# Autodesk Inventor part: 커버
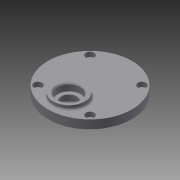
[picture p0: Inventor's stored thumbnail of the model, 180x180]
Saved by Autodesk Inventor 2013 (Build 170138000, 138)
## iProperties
Created: 2015-07
Part Number: 커버
Material: 일반
Document SubType Name: Modeling
Designer: user
Density: 1 g/cm^3
Author: user
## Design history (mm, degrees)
sketch "스케치1"
  geometry: C1 r 40 at (0, 0); 1 further point
  constraints: 1 centre point, 1 coincident
  dimensions: "d0" = 80 diameter of C1
extrude "돌출1" new body sketch "스케치1" distance "d1" = 9; taper "d2" = 0 deg
sketch "스케치2"
  geometry: L1 (0, 0)-(0, 11); L2 (0, 0)-(0, -20); C1 r 40 at (0, 0) reference; C2 r 14 at (0, -20); C3 r 14 at (0, 11)
  constraints: 4 end point, 2 centre point, 2 coincident, 1 collinear, 1 vertical
  dimensions: "d3" = 11 distance of L1.start L1.end; "d4" = 20 distance of L1.start L2.end; "d6" = 28 diameter of C2; "d7" = 28 diameter of C3
extrude "돌출2" join sketch "스케치2" distance "d8" = 3; taper "d9" = 0 deg
sketch "스케치3"
  geometry: C1 r 14 at (0, 0) reference; C2 r 11 at (0, 0); 1 further point
  constraints: 1 centre point, 1 coincident
  dimensions: "d10" = 22 diameter of C2
extrude "돌출3" cut sketch "스케치3" distance "d11" = 7; taper "d12" = 0 deg
sketch "스케치4"
  geometry: C1 r 9 at (0, 0); 2 further points
  constraints: 1 centre point, 1 coincident, 1 vertical alignment
  dimensions: "d13" = 18 diameter of C1
extrude "돌출4" cut sketch "스케치4" distance "d14" = 1; taper "d15" = 0 deg
sketch "스케치5"
  geometry: L1 (0, 0)-(0, -20); C1 r 40 at (0, 0) reference; C2 r 15 at (0, -20)
  constraints: 2 end point, 1 centre point, 1 coincident, 1 vertical
  dimensions: "d16" = 20 distance of L1.start L1.end; "d17" = 30 diameter of C2
extrude "돌출5" join sketch "스케치5" distance "d18" = 4; taper "d19" = 0 deg
sketch "스케치6"
  geometry: C1 r 14 at (0, 0) reference; C2 r 11 at (0, 0); 1 further point
  constraints: 1 centre point, 1 coincident
  dimensions: "d20" = 22 diameter of C2
extrude "돌출6" cut sketch "스케치6" distance "d21" = 7; taper "d22" = 0 deg
sketch "스케치7"
  geometry: C1 r 11 at (0, 0) reference; C2 r 7.5 at (0, 0); 1 further point
  constraints: 1 centre point, 1 coincident
  dimensions: "d23" = 15 diameter of C2
extrude "돌출7" cut sketch "스케치7" distance "d24" = 2; taper "d25" = 0 deg
sketch "스케치8"
  geometry: C1 r 7.5 at (0, 0) reference; C2 r 11 at (0, 0); 1 further point
  constraints: 1 centre point, 1 coincident
  dimensions: "d26" = 22 diameter of C2
extrude "돌출8" cut sketch "스케치8" distance "d27" = 7; taper "d28" = 0 deg
chamfer "모따기1" distance "d29" = 1; stored, may be unused: second distance "d30" = 2, angle "d31" = 45 deg
fillet "모깎기1" dims "d32" = 0.3
sketch "스케치9"
  geometry: L1 (0, 0)-(35, 0); L2 (0, 0)-(24.749, 24.749); C1 r 40 at (0, 0) reference; A1 r 35 centre (0, 0) between (35, 0) and (24.749, 24.749); 1 further point
  constraints: 4 end point, 2 coincident, 2 point on circle, 1 centre point, 1 horizontal
  dimensions: "d33" = 70 diameter of A1; "d34" = 45 deg angle of L1 L2
hole "구멍1" sketch "스케치9" at (24.749, 24.749) diameter "d36" = 4.5; stored, may be unused: countersink angle "d40" = 90 deg, drill point angle "d42" = 118 deg; dims "d37" = 6, "d38" = 8, "d39" = 4.4, "d41" = 8
fillet "모깎기2" dims "d46" = 2
chamfer "모따기2" distance "d47" = 1; stored, may be unused: second distance "d48" = 2, angle "d49" = 45 deg
node "솔리드1"
pattern_circular "원형 패턴1" dims angle "d44" = 360 deg
